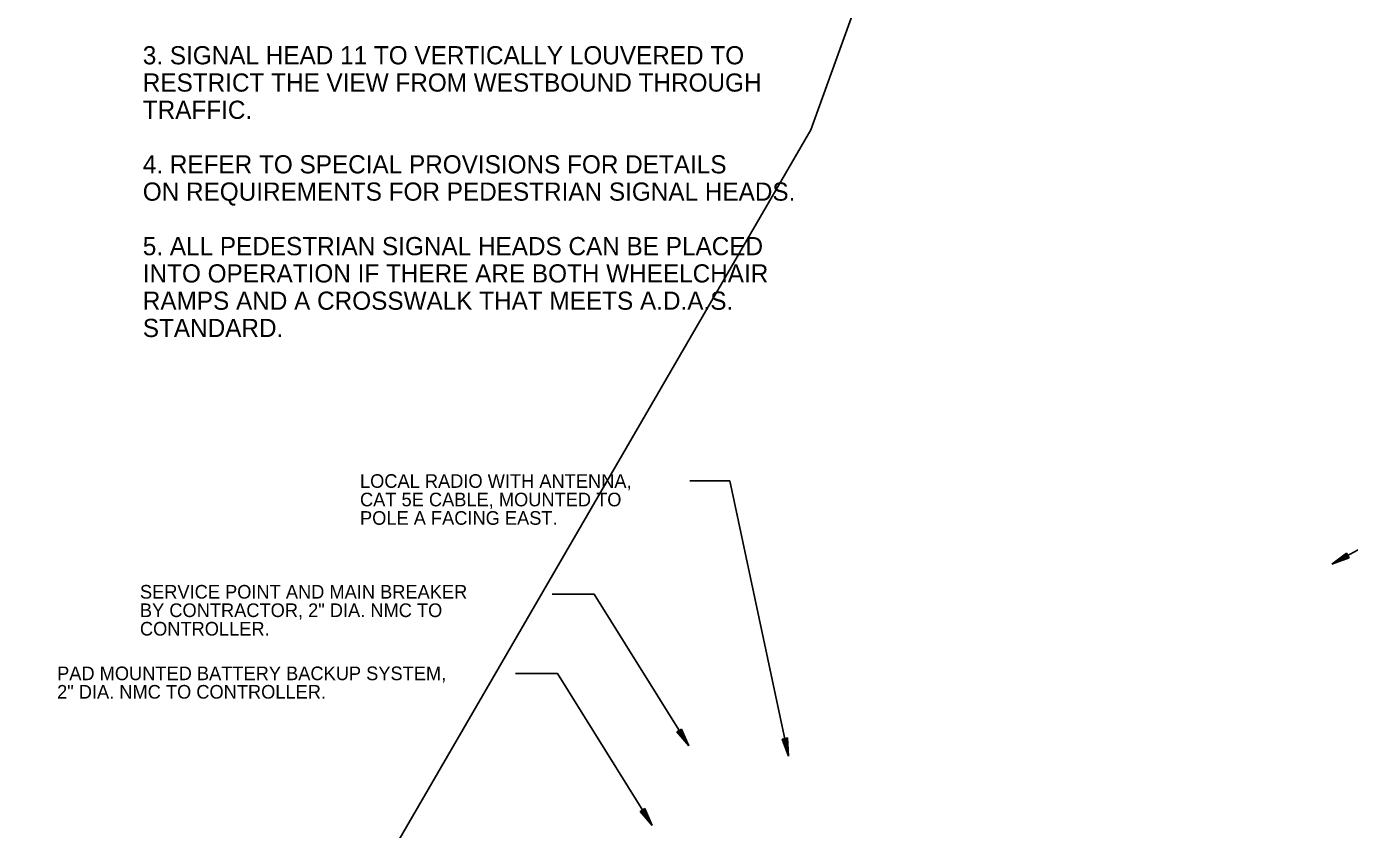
# Model space of a CAD drawing. Extents: x 660063 to 664816, y 641756 to 643817.
# Drawn here: x 661614.4 to 661905.5, y 642548.1 to 642724.8 of the extents above; entities that cross this region are included whole.
import ezdxf

# ---------------------------------------------------------------- set-up
doc = ezdxf.new("R2010")
doc.units = 0
doc.layers.add('T_Drafting', color=7, linetype='Continuous')
doc.layers.add('T_Notes', color=7, linetype='Continuous')

msp = doc.modelspace()

# ---------------------------------------------------------------- linework, layer by layer
at = {"layer": 'T_Drafting'}
for p, q in [((661769.1, 642624.82), (661760.36, 642624.82)), ((661769.1, 642624.82), (661782.07, 642564.21)), ((661929.59, 642621.84), (661901.56, 642606.48)), ((661904.78, 642608.93), (661901.56, 642606.48)), ((661905.36, 642607.88), (661901.56, 642606.48)), ((661904.83, 642608.84), (661902.15, 642606.8)), ((661905.31, 642607.96), (661902.15, 642606.8)), ((661904.88, 642608.75), (661902.75, 642607.13)), ((661905.26, 642608.05), (661902.75, 642607.13)), ((661904.92, 642608.66), (661903.33, 642607.45)), ((661905.21, 642608.14), (661903.33, 642607.45)), ((661904.97, 642608.57), (661903.93, 642607.78)), ((661905.16, 642608.23), (661903.93, 642607.78)), ((661905.02, 642608.48), (661904.51, 642608.1)), ((661905.11, 642608.32), (661904.51, 642608.1)), ((661905.36, 642607.88), (661904.78, 642608.93)), ((661739.27, 642599.9), (661730.05, 642599.9)), ((661739.27, 642599.9), (661760.1, 642566.48)), ((661731.23, 642582.41), (661722.01, 642582.41)), ((661731.23, 642582.41), (661752.06, 642548.99)), ((661758.5, 642570.19), (661757.48, 642569.56)), ((661758.24, 642570.03), (661759.03, 642568.2)), ((661758.33, 642570.09), (661759.39, 642567.63)), ((661758.41, 642570.14), (661759.75, 642567.05)), ((661758.5, 642570.19), (661760.1, 642566.48)), ((661757.48, 642569.56), (661760.1, 642566.48)), ((661757.56, 642569.61), (661759.75, 642567.05)), ((661757.65, 642569.67), (661759.39, 642567.63)), ((661757.74, 642569.72), (661759.03, 642568.2)), ((661757.82, 642569.77), (661758.68, 642568.77)), ((661757.91, 642569.83), (661758.32, 642569.34)), ((661758.07, 642569.93), (661758.32, 642569.34)), ((661758.15, 642569.98), (661758.68, 642568.77)), ((661781.82, 642568.25), (661780.65, 642568)), ((661780.65, 642568), (661782.07, 642564.21)), ((661780.75, 642568.02), (661781.93, 642564.86)), ((661780.85, 642568.04), (661781.79, 642565.54)), ((661780.94, 642568.06), (661781.65, 642566.19)), ((661781.04, 642568.08), (661781.51, 642566.85)), ((661781.14, 642568.1), (661781.37, 642567.5)), ((661781.33, 642568.14), (661781.37, 642567.5)), ((661781.42, 642568.16), (661781.51, 642566.85)), ((661781.53, 642568.18), (661781.65, 642566.19)), ((661781.62, 642568.21), (661781.79, 642565.54)), ((661781.72, 642568.23), (661781.93, 642564.86)), ((661781.82, 642568.25), (661782.07, 642564.21)), ((661750.46, 642552.7), (661749.44, 642552.07)), ((661750.2, 642552.54), (661750.99, 642550.7)), ((661750.28, 642552.59), (661751.35, 642550.14)), ((661750.37, 642552.65), (661751.71, 642549.55)), ((661750.46, 642552.7), (661752.06, 642548.99)), ((661749.44, 642552.07), (661752.06, 642548.99)), ((661749.52, 642552.12), (661751.71, 642549.55)), ((661749.61, 642552.17), (661751.35, 642550.14)), ((661749.69, 642552.22), (661750.99, 642550.7)), ((661749.78, 642552.28), (661750.63, 642551.28)), ((661749.87, 642552.33), (661750.28, 642551.85)), ((661750.03, 642552.43), (661750.28, 642551.85)), ((661750.11, 642552.49), (661750.63, 642551.28))]:
    msp.add_line(p, q, dxfattribs=at)
msp.add_lwpolyline([(661903.35, 643024.49), (661786.96, 642702.02), (661273.12, 641816.18)], dxfattribs=at)
msp.add_lwpolyline([(661903.35, 643024.49), (661786.96, 642702.02), (661273.12, 641816.18)], dxfattribs=at)
msp.add_lwpolyline([(661903.35, 643024.49), (661786.96, 642702.02), (661273.12, 641816.18)], dxfattribs=at)

# ---------------------------------------------------------------- texts
for s, p in [('LOCAL RADIO WITH ANTENNA,', (661687.78, 642623.28)), ('CAT 5E CABLE, MOUNTED TO', (661687.78, 642619.21)), ('POLE A FACING EAST.', (661687.78, 642615.15)), ('SERVICE POINT AND MAIN BREAKER', (661639.37, 642598.91)), ('BY CONTRACTOR, 2" DIA. NMC TO', (661639.37, 642594.85)), ('CONTROLLER.', (661639.37, 642590.78)), ('PAD MOUNTED BATTERY BACKUP SYSTEM, ', (661621.15, 642580.96)), ('2" DIA. NMC TO CONTROLLER.', (661621.15, 642576.9))]:
    msp.add_text(s, height=3, dxfattribs=at).set_placement(p)
at = {"layer": 'T_Notes'}
for s, p in [('3. SIGNAL HEAD 11 TO VERTICALLY LOUVERED TO', (661640, 642716.46)), ('RESTRICT THE VIEW FROM WESTBOUND THROUGH', (661640, 642710.46)), ('TRAFFIC.', (661640, 642704.46)), ('4. REFER TO SPECIAL PROVISIONS FOR DETAILS', (661640, 642692.46)), ('ON REQUIREMENTS FOR PEDESTRIAN SIGNAL HEADS.', (661640, 642686.46)), ('5. ALL PEDESTRIAN SIGNAL HEADS CAN BE PLACED', (661640, 642674.46)), ('INTO OPERATION IF THERE ARE BOTH WHEELCHAIR', (661640, 642668.46)), ('RAMPS AND A CROSSWALK THAT MEETS A.D.A.S.', (661640, 642662.46)), ('STANDARD.', (661640, 642656.46))]:
    msp.add_text(s, height=4, dxfattribs=at).set_placement(p)

doc.saveas('drawing.dxf')
